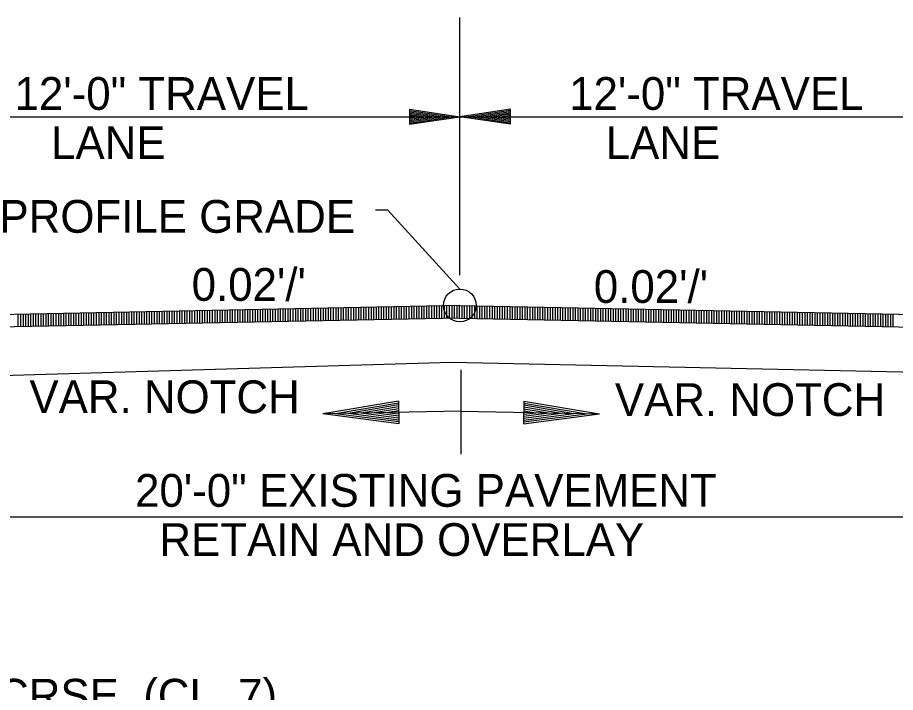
# Model space of a CAD drawing. Extents: x 1373719 to 1374161, y 379835 to 380167.
# Drawn here: x 1373956.25 to 1373973.66, y 380106.35 to 380119.74 of the extents above; entities that cross this region are included whole.
import ezdxf

# ---------------------------------------------------------------- set-up
doc = ezdxf.new("R2010")
doc.units = 0
for name, color, linetype in [('ACHM Surface', 7, 'Continuous'), ('Agg Base Course Text', 7, 'Continuous'), ('CL Construction', 7, 'Continuous'), ('GREEN_TXT', 7, 'Continuous'), ('T_Drafting', 7, 'Continuous')]:
    doc.layers.add(name, color=color, linetype=linetype)

msp = doc.modelspace()

# ---------------------------------------------------------------- linework, layer by layer
for p, q in [((1373965.018, 380114.03), (1373954.02, 380113.81)), ((1373965.018, 380114.03), (1373976.015, 380113.81)), ((1373965.018, 380113.78), (1373954.02, 380113.56)), ((1373965.018, 380113.78), (1373976.015, 380113.56))]:
    msp.add_line(p, q)
at = {"layer": 'ACHM Surface'}
for p, q in [((1373957.813, 380113.636), (1373957.813, 380113.886)), ((1373957.863, 380113.637), (1373957.863, 380113.887)), ((1373957.913, 380113.638), (1373957.913, 380113.888)), ((1373957.963, 380113.639), (1373957.963, 380113.889)), ((1373958.013, 380113.64), (1373958.013, 380113.89)), ((1373958.063, 380113.641), (1373958.063, 380113.891)), ((1373958.113, 380113.642), (1373958.113, 380113.892)), ((1373958.163, 380113.643), (1373958.163, 380113.893)), ((1373958.213, 380113.644), (1373958.213, 380113.894)), ((1373958.263, 380113.645), (1373958.263, 380113.895)), ((1373958.313, 380113.646), (1373958.313, 380113.896)), ((1373958.363, 380113.647), (1373958.363, 380113.897)), ((1373958.413, 380113.648), (1373958.413, 380113.898)), ((1373958.463, 380113.649), (1373958.463, 380113.899)), ((1373958.513, 380113.65), (1373958.513, 380113.9)), ((1373958.563, 380113.651), (1373958.563, 380113.901)), ((1373958.613, 380113.652), (1373958.613, 380113.902)), ((1373958.663, 380113.653), (1373958.663, 380113.903)), ((1373958.713, 380113.654), (1373958.713, 380113.904)), ((1373958.763, 380113.655), (1373958.763, 380113.905)), ((1373958.813, 380113.656), (1373958.813, 380113.906)), ((1373958.863, 380113.657), (1373958.863, 380113.907)), ((1373958.913, 380113.658), (1373958.913, 380113.908)), ((1373958.963, 380113.659), (1373958.963, 380113.909)), ((1373959.013, 380113.66), (1373959.013, 380113.91)), ((1373959.063, 380113.661), (1373959.063, 380113.911)), ((1373959.113, 380113.662), (1373959.113, 380113.912)), ((1373959.163, 380113.663), (1373959.163, 380113.913)), ((1373959.213, 380113.664), (1373959.213, 380113.914)), ((1373959.263, 380113.665), (1373959.263, 380113.915)), ((1373959.313, 380113.666), (1373959.313, 380113.916)), ((1373959.363, 380113.667), (1373959.363, 380113.917)), ((1373959.413, 380113.668), (1373959.413, 380113.918)), ((1373959.463, 380113.669), (1373959.463, 380113.919)), ((1373959.513, 380113.67), (1373959.513, 380113.92)), ((1373959.563, 380113.671), (1373959.563, 380113.921)), ((1373959.613, 380113.672), (1373959.613, 380113.922)), ((1373959.663, 380113.673), (1373959.663, 380113.923)), ((1373959.713, 380113.674), (1373959.713, 380113.924)), ((1373959.763, 380113.675), (1373959.763, 380113.925)), ((1373959.813, 380113.676), (1373959.813, 380113.926)), ((1373959.863, 380113.677), (1373959.863, 380113.927)), ((1373959.913, 380113.678), (1373959.913, 380113.928)), ((1373959.963, 380113.679), (1373959.963, 380113.929)), ((1373960.013, 380113.68), (1373960.013, 380113.93)), ((1373960.063, 380113.681), (1373960.063, 380113.931)), ((1373960.113, 380113.682), (1373960.113, 380113.932)), ((1373960.163, 380113.683), (1373960.163, 380113.933)), ((1373960.213, 380113.684), (1373960.213, 380113.934)), ((1373960.263, 380113.685), (1373960.263, 380113.935)), ((1373960.313, 380113.686), (1373960.313, 380113.936)), ((1373960.363, 380113.687), (1373960.363, 380113.937)), ((1373960.413, 380113.688), (1373960.413, 380113.938)), ((1373960.463, 380113.689), (1373960.463, 380113.939)), ((1373960.513, 380113.69), (1373960.513, 380113.94)), ((1373960.563, 380113.691), (1373960.563, 380113.941)), ((1373960.613, 380113.692), (1373960.613, 380113.942)), ((1373960.663, 380113.693), (1373960.663, 380113.943)), ((1373960.713, 380113.694), (1373960.713, 380113.944)), ((1373960.763, 380113.695), (1373960.763, 380113.945)), ((1373960.813, 380113.696), (1373960.813, 380113.946)), ((1373960.863, 380113.697), (1373960.863, 380113.947)), ((1373960.913, 380113.698), (1373960.913, 380113.948)), ((1373960.963, 380113.699), (1373960.963, 380113.949)), ((1373961.013, 380113.7), (1373961.013, 380113.95)), ((1373961.063, 380113.701), (1373961.063, 380113.951)), ((1373961.113, 380113.702), (1373961.113, 380113.952)), ((1373961.163, 380113.703), (1373961.163, 380113.953)), ((1373961.213, 380113.704), (1373961.213, 380113.954)), ((1373961.263, 380113.705), (1373961.263, 380113.955)), ((1373961.313, 380113.706), (1373961.313, 380113.956)), ((1373961.363, 380113.707), (1373961.363, 380113.957)), ((1373961.413, 380113.708), (1373961.413, 380113.958)), ((1373961.463, 380113.709), (1373961.463, 380113.959)), ((1373961.513, 380113.71), (1373961.513, 380113.96)), ((1373961.563, 380113.711), (1373961.563, 380113.961)), ((1373961.613, 380113.712), (1373961.613, 380113.962)), ((1373961.663, 380113.713), (1373961.663, 380113.963)), ((1373961.713, 380113.714), (1373961.713, 380113.964)), ((1373961.763, 380113.715), (1373961.763, 380113.965)), ((1373961.813, 380113.716), (1373961.813, 380113.966)), ((1373961.863, 380113.717), (1373961.863, 380113.967)), ((1373961.913, 380113.718), (1373961.913, 380113.968)), ((1373961.963, 380113.719), (1373961.963, 380113.969)), ((1373962.013, 380113.72), (1373962.013, 380113.97)), ((1373962.063, 380113.721), (1373962.063, 380113.971)), ((1373962.113, 380113.722), (1373962.113, 380113.972)), ((1373962.163, 380113.723), (1373962.163, 380113.973)), ((1373962.213, 380113.724), (1373962.213, 380113.974)), ((1373962.263, 380113.725), (1373962.263, 380113.975)), ((1373962.313, 380113.726), (1373962.313, 380113.976)), ((1373962.363, 380113.727), (1373962.363, 380113.977)), ((1373962.413, 380113.728), (1373962.413, 380113.978)), ((1373962.463, 380113.729), (1373962.463, 380113.979)), ((1373962.513, 380113.73), (1373962.513, 380113.98)), ((1373962.563, 380113.731), (1373962.563, 380113.981)), ((1373962.613, 380113.732), (1373962.613, 380113.982)), ((1373962.663, 380113.733), (1373962.663, 380113.983)), ((1373962.713, 380113.734), (1373962.713, 380113.984)), ((1373962.763, 380113.735), (1373962.763, 380113.985)), ((1373962.813, 380113.736), (1373962.813, 380113.986)), ((1373962.863, 380113.737), (1373962.863, 380113.987)), ((1373962.913, 380113.738), (1373962.913, 380113.988)), ((1373962.963, 380113.739), (1373962.963, 380113.989)), ((1373963.013, 380113.74), (1373963.013, 380113.99)), ((1373963.063, 380113.741), (1373963.063, 380113.991)), ((1373963.113, 380113.742), (1373963.113, 380113.992)), ((1373963.163, 380113.743), (1373963.163, 380113.993)), ((1373963.213, 380113.744), (1373963.213, 380113.994)), ((1373963.263, 380113.745), (1373963.263, 380113.995)), ((1373963.313, 380113.746), (1373963.313, 380113.996)), ((1373963.363, 380113.747), (1373963.363, 380113.997)), ((1373963.413, 380113.748), (1373963.413, 380113.998)), ((1373963.463, 380113.749), (1373963.463, 380113.999)), ((1373963.513, 380113.75), (1373963.513, 380114)), ((1373963.563, 380113.751), (1373963.563, 380114.001)), ((1373963.613, 380113.752), (1373963.613, 380114.002)), ((1373963.663, 380113.753), (1373963.663, 380114.003)), ((1373963.713, 380113.754), (1373963.713, 380114.004)), ((1373963.763, 380113.755), (1373963.763, 380114.005)), ((1373963.813, 380113.756), (1373963.813, 380114.006)), ((1373963.863, 380113.757), (1373963.863, 380114.007)), ((1373963.913, 380113.758), (1373963.913, 380114.008)), ((1373963.963, 380113.759), (1373963.963, 380114.009)), ((1373964.013, 380113.76), (1373964.013, 380114.01)), ((1373964.063, 380113.761), (1373964.063, 380114.011)), ((1373964.113, 380113.762), (1373964.113, 380114.012)), ((1373964.163, 380113.763), (1373964.163, 380114.013)), ((1373964.213, 380113.764), (1373964.213, 380114.014)), ((1373964.263, 380113.765), (1373964.263, 380114.015)), ((1373964.313, 380113.766), (1373964.313, 380114.016)), ((1373964.363, 380113.767), (1373964.363, 380114.017)), ((1373964.413, 380113.768), (1373964.413, 380114.018)), ((1373964.463, 380113.769), (1373964.463, 380114.019)), ((1373964.513, 380113.77), (1373964.513, 380114.02)), ((1373964.563, 380113.771), (1373964.563, 380114.021)), ((1373964.613, 380113.772), (1373964.613, 380114.022)), ((1373964.663, 380113.773), (1373964.663, 380114.023)), ((1373964.713, 380113.774), (1373964.713, 380114.024)), ((1373964.763, 380113.775), (1373964.763, 380114.025)), ((1373964.813, 380113.776), (1373964.813, 380114.026)), ((1373964.863, 380113.777), (1373964.863, 380114.027)), ((1373964.913, 380113.778), (1373964.913, 380114.028)), ((1373964.963, 380113.779), (1373964.963, 380114.029)), ((1373965.013, 380113.78), (1373965.013, 380114.03)), ((1373965.063, 380113.779), (1373965.063, 380114.029)), ((1373965.113, 380113.778), (1373965.113, 380114.028)), ((1373965.163, 380113.777), (1373965.163, 380114.027)), ((1373965.213, 380113.776), (1373965.213, 380114.026)), ((1373965.263, 380113.775), (1373965.263, 380114.025)), ((1373965.313, 380113.774), (1373965.313, 380114.024)), ((1373965.363, 380113.773), (1373965.363, 380114.023)), ((1373965.413, 380113.772), (1373965.413, 380114.022)), ((1373965.463, 380113.771), (1373965.463, 380114.021)), ((1373965.513, 380113.77), (1373965.513, 380114.02)), ((1373965.563, 380113.769), (1373965.563, 380114.019)), ((1373965.613, 380113.768), (1373965.613, 380114.018)), ((1373965.663, 380113.767), (1373965.663, 380114.017)), ((1373965.713, 380113.766), (1373965.713, 380114.016)), ((1373965.763, 380113.765), (1373965.763, 380114.015)), ((1373965.813, 380113.764), (1373965.813, 380114.014)), ((1373965.863, 380113.763), (1373965.863, 380114.013)), ((1373965.913, 380113.762), (1373965.913, 380114.012)), ((1373965.963, 380113.761), (1373965.963, 380114.011)), ((1373966.013, 380113.76), (1373966.013, 380114.01)), ((1373966.063, 380113.759), (1373966.063, 380114.009)), ((1373966.113, 380113.758), (1373966.113, 380114.008)), ((1373966.163, 380113.757), (1373966.163, 380114.007)), ((1373966.213, 380113.756), (1373966.213, 380114.006)), ((1373966.263, 380113.755), (1373966.263, 380114.005)), ((1373966.313, 380113.754), (1373966.313, 380114.004)), ((1373966.363, 380113.753), (1373966.363, 380114.003)), ((1373966.413, 380113.752), (1373966.413, 380114.002)), ((1373966.463, 380113.751), (1373966.463, 380114.001)), ((1373966.513, 380113.75), (1373966.513, 380114)), ((1373966.563, 380113.749), (1373966.563, 380113.999)), ((1373966.613, 380113.748), (1373966.613, 380113.998)), ((1373966.663, 380113.747), (1373966.663, 380113.997)), ((1373966.713, 380113.746), (1373966.713, 380113.996)), ((1373966.763, 380113.745), (1373966.763, 380113.995)), ((1373966.813, 380113.744), (1373966.813, 380113.994)), ((1373966.863, 380113.743), (1373966.863, 380113.993)), ((1373966.913, 380113.742), (1373966.913, 380113.992)), ((1373966.963, 380113.741), (1373966.963, 380113.991)), ((1373967.013, 380113.74), (1373967.013, 380113.99)), ((1373967.063, 380113.739), (1373967.063, 380113.989)), ((1373967.113, 380113.738), (1373967.113, 380113.988)), ((1373967.163, 380113.737), (1373967.163, 380113.987)), ((1373967.213, 380113.736), (1373967.213, 380113.986)), ((1373967.263, 380113.735), (1373967.263, 380113.985)), ((1373967.313, 380113.734), (1373967.313, 380113.984)), ((1373967.363, 380113.733), (1373967.363, 380113.983)), ((1373967.413, 380113.732), (1373967.413, 380113.982)), ((1373967.463, 380113.731), (1373967.463, 380113.981)), ((1373967.513, 380113.73), (1373967.513, 380113.98)), ((1373967.563, 380113.729), (1373967.563, 380113.979)), ((1373967.613, 380113.728), (1373967.613, 380113.978)), ((1373967.663, 380113.727), (1373967.663, 380113.977)), ((1373967.713, 380113.726), (1373967.713, 380113.976)), ((1373967.763, 380113.725), (1373967.763, 380113.975)), ((1373967.813, 380113.724), (1373967.813, 380113.974)), ((1373967.863, 380113.723), (1373967.863, 380113.973)), ((1373967.913, 380113.722), (1373967.913, 380113.972)), ((1373967.963, 380113.721), (1373967.963, 380113.971)), ((1373968.013, 380113.72), (1373968.013, 380113.97)), ((1373968.063, 380113.719), (1373968.063, 380113.969)), ((1373968.113, 380113.718), (1373968.113, 380113.968)), ((1373968.163, 380113.717), (1373968.163, 380113.967)), ((1373968.213, 380113.716), (1373968.213, 380113.966)), ((1373968.263, 380113.715), (1373968.263, 380113.965)), ((1373968.313, 380113.714), (1373968.313, 380113.964)), ((1373968.363, 380113.713), (1373968.363, 380113.963)), ((1373968.413, 380113.712), (1373968.413, 380113.962)), ((1373968.463, 380113.711), (1373968.463, 380113.961)), ((1373968.513, 380113.71), (1373968.513, 380113.96)), ((1373968.563, 380113.709), (1373968.563, 380113.959)), ((1373968.613, 380113.708), (1373968.613, 380113.958)), ((1373968.663, 380113.707), (1373968.663, 380113.957)), ((1373968.713, 380113.706), (1373968.713, 380113.956)), ((1373968.763, 380113.705), (1373968.763, 380113.955)), ((1373968.813, 380113.704), (1373968.813, 380113.954)), ((1373968.863, 380113.703), (1373968.863, 380113.953)), ((1373968.913, 380113.702), (1373968.913, 380113.952)), ((1373968.963, 380113.701), (1373968.963, 380113.951)), ((1373969.013, 380113.7), (1373969.013, 380113.95)), ((1373969.063, 380113.699), (1373969.063, 380113.949)), ((1373969.113, 380113.698), (1373969.113, 380113.948)), ((1373969.163, 380113.697), (1373969.163, 380113.947)), ((1373969.213, 380113.696), (1373969.213, 380113.946)), ((1373969.263, 380113.695), (1373969.263, 380113.945)), ((1373969.313, 380113.694), (1373969.313, 380113.944)), ((1373969.363, 380113.693), (1373969.363, 380113.943)), ((1373969.413, 380113.692), (1373969.413, 380113.942)), ((1373969.463, 380113.691), (1373969.463, 380113.941)), ((1373969.513, 380113.69), (1373969.513, 380113.94)), ((1373969.563, 380113.689), (1373969.563, 380113.939)), ((1373969.613, 380113.688), (1373969.613, 380113.938)), ((1373969.663, 380113.687), (1373969.663, 380113.937)), ((1373969.713, 380113.686), (1373969.713, 380113.936)), ((1373969.763, 380113.685), (1373969.763, 380113.935)), ((1373969.813, 380113.684), (1373969.813, 380113.934)), ((1373969.863, 380113.683), (1373969.863, 380113.933)), ((1373969.913, 380113.682), (1373969.913, 380113.932)), ((1373969.963, 380113.681), (1373969.963, 380113.931)), ((1373970.013, 380113.68), (1373970.013, 380113.93)), ((1373970.063, 380113.679), (1373970.063, 380113.929)), ((1373970.113, 380113.678), (1373970.113, 380113.928)), ((1373970.163, 380113.677), (1373970.163, 380113.927)), ((1373970.213, 380113.676), (1373970.213, 380113.926)), ((1373970.263, 380113.675), (1373970.263, 380113.925)), ((1373970.313, 380113.674), (1373970.313, 380113.924)), ((1373970.363, 380113.673), (1373970.363, 380113.923)), ((1373970.413, 380113.672), (1373970.413, 380113.922)), ((1373970.463, 380113.671), (1373970.463, 380113.921)), ((1373970.513, 380113.67), (1373970.513, 380113.92)), ((1373970.563, 380113.669), (1373970.563, 380113.919)), ((1373970.613, 380113.668), (1373970.613, 380113.918)), ((1373970.663, 380113.667), (1373970.663, 380113.917)), ((1373970.713, 380113.666), (1373970.713, 380113.916)), ((1373970.763, 380113.665), (1373970.763, 380113.915)), ((1373970.813, 380113.664), (1373970.813, 380113.914)), ((1373970.863, 380113.663), (1373970.863, 380113.913)), ((1373970.913, 380113.662), (1373970.913, 380113.912)), ((1373970.963, 380113.661), (1373970.963, 380113.911)), ((1373971.013, 380113.66), (1373971.013, 380113.91)), ((1373971.063, 380113.659), (1373971.063, 380113.909)), ((1373971.113, 380113.658), (1373971.113, 380113.908)), ((1373971.163, 380113.657), (1373971.163, 380113.907)), ((1373971.213, 380113.656), (1373971.213, 380113.906)), ((1373971.263, 380113.655), (1373971.263, 380113.905)), ((1373971.313, 380113.654), (1373971.313, 380113.904)), ((1373971.363, 380113.653), (1373971.363, 380113.903)), ((1373971.413, 380113.652), (1373971.413, 380113.902)), ((1373971.463, 380113.651), (1373971.463, 380113.901)), ((1373971.513, 380113.65), (1373971.513, 380113.9)), ((1373971.563, 380113.649), (1373971.563, 380113.899)), ((1373971.613, 380113.648), (1373971.613, 380113.898)), ((1373971.663, 380113.647), (1373971.663, 380113.897)), ((1373971.713, 380113.646), (1373971.713, 380113.896)), ((1373971.763, 380113.645), (1373971.763, 380113.895)), ((1373971.813, 380113.644), (1373971.813, 380113.894)), ((1373971.863, 380113.643), (1373971.863, 380113.893)), ((1373971.913, 380113.642), (1373971.913, 380113.892)), ((1373971.963, 380113.641), (1373971.963, 380113.891)), ((1373972.013, 380113.64), (1373972.013, 380113.89)), ((1373972.063, 380113.639), (1373972.063, 380113.889)), ((1373972.113, 380113.638), (1373972.113, 380113.888)), ((1373972.163, 380113.637), (1373972.163, 380113.887)), ((1373972.213, 380113.636), (1373972.213, 380113.886)), ((1373956.263, 380113.605), (1373956.263, 380113.855)), ((1373956.313, 380113.606), (1373956.313, 380113.856)), ((1373956.363, 380113.607), (1373956.363, 380113.857)), ((1373956.413, 380113.608), (1373956.413, 380113.858)), ((1373956.463, 380113.609), (1373956.463, 380113.859)), ((1373956.513, 380113.61), (1373956.513, 380113.86)), ((1373956.563, 380113.611), (1373956.563, 380113.861)), ((1373956.613, 380113.612), (1373956.613, 380113.862)), ((1373956.663, 380113.613), (1373956.663, 380113.863)), ((1373956.713, 380113.614), (1373956.713, 380113.864)), ((1373956.763, 380113.615), (1373956.763, 380113.865)), ((1373956.813, 380113.616), (1373956.813, 380113.866)), ((1373956.863, 380113.617), (1373956.863, 380113.867)), ((1373956.913, 380113.618), (1373956.913, 380113.868)), ((1373956.963, 380113.619), (1373956.963, 380113.869)), ((1373957.013, 380113.62), (1373957.013, 380113.87)), ((1373957.063, 380113.621), (1373957.063, 380113.871)), ((1373957.113, 380113.622), (1373957.113, 380113.872)), ((1373957.163, 380113.623), (1373957.163, 380113.873)), ((1373957.213, 380113.624), (1373957.213, 380113.874)), ((1373957.263, 380113.625), (1373957.263, 380113.875)), ((1373957.313, 380113.626), (1373957.313, 380113.876)), ((1373957.363, 380113.627), (1373957.363, 380113.877)), ((1373957.413, 380113.628), (1373957.413, 380113.878)), ((1373957.463, 380113.629), (1373957.463, 380113.879)), ((1373957.513, 380113.63), (1373957.513, 380113.88)), ((1373957.563, 380113.631), (1373957.563, 380113.881)), ((1373957.613, 380113.632), (1373957.613, 380113.882)), ((1373957.663, 380113.633), (1373957.663, 380113.883)), ((1373957.713, 380113.634), (1373957.713, 380113.884)), ((1373957.763, 380113.635), (1373957.763, 380113.885)), ((1373972.263, 380113.635), (1373972.263, 380113.885)), ((1373972.313, 380113.634), (1373972.313, 380113.884)), ((1373972.363, 380113.633), (1373972.363, 380113.883)), ((1373972.413, 380113.632), (1373972.413, 380113.882)), ((1373972.463, 380113.631), (1373972.463, 380113.881)), ((1373972.513, 380113.63), (1373972.513, 380113.88)), ((1373972.563, 380113.629), (1373972.563, 380113.879)), ((1373972.613, 380113.628), (1373972.613, 380113.878)), ((1373972.663, 380113.627), (1373972.663, 380113.877)), ((1373972.713, 380113.626), (1373972.713, 380113.876)), ((1373972.763, 380113.625), (1373972.763, 380113.875)), ((1373972.813, 380113.624), (1373972.813, 380113.874)), ((1373972.863, 380113.623), (1373972.863, 380113.873)), ((1373972.913, 380113.622), (1373972.913, 380113.872)), ((1373972.963, 380113.621), (1373972.963, 380113.871)), ((1373973.013, 380113.62), (1373973.013, 380113.87)), ((1373973.063, 380113.619), (1373973.063, 380113.869)), ((1373973.113, 380113.618), (1373973.113, 380113.868)), ((1373973.163, 380113.617), (1373973.163, 380113.867)), ((1373973.213, 380113.616), (1373973.213, 380113.866)), ((1373973.263, 380113.615), (1373973.263, 380113.865)), ((1373973.313, 380113.614), (1373973.313, 380113.864)), ((1373973.363, 380113.613), (1373973.363, 380113.863)), ((1373973.413, 380113.612), (1373973.413, 380113.862)), ((1373973.463, 380113.611), (1373973.463, 380113.861)), ((1373973.513, 380113.61), (1373973.513, 380113.86)), ((1373973.563, 380113.609), (1373973.563, 380113.859)), ((1373973.613, 380113.608), (1373973.613, 380113.858))]:
    msp.add_line(p, q, dxfattribs=at)
at = {"layer": 'CL Construction'}
msp.add_line((1373965.018, 380114.627), (1373965.018, 380119.74), dxfattribs=at)
at = {"layer": 'GREEN_TXT'}
for p, q in [((1373964.02, 380117.922), (1373965.02, 380117.772)), ((1373964.02, 380117.922), (1373964.02, 380117.622)), ((1373964.02, 380117.897), (1373964.853, 380117.772)), ((1373966.02, 380117.922), (1373965.02, 380117.772)), ((1373966.02, 380117.897), (1373965.187, 380117.772)), ((1373966.02, 380117.622), (1373966.02, 380117.922)), ((1373954.02, 380117.772), (1373976.02, 380117.772)), ((1373964.02, 380117.871), (1373964.681, 380117.772)), ((1373964.02, 380117.846), (1373964.514, 380117.772)), ((1373964.02, 380117.82), (1373964.345, 380117.772)), ((1373964.02, 380117.795), (1373964.178, 380117.772)), ((1373964.02, 380117.622), (1373965.02, 380117.772)), ((1373964.02, 380117.723), (1373964.345, 380117.772)), ((1373964.02, 380117.672), (1373964.681, 380117.772)), ((1373964.02, 380117.647), (1373964.853, 380117.772)), ((1373964.02, 380117.697), (1373964.514, 380117.772)), ((1373964.02, 380117.748), (1373964.178, 380117.772)), ((1373966.02, 380117.622), (1373965.02, 380117.772)), ((1373966.02, 380117.647), (1373965.187, 380117.772)), ((1373966.02, 380117.871), (1373965.359, 380117.772)), ((1373966.02, 380117.672), (1373965.359, 380117.772)), ((1373966.02, 380117.846), (1373965.525, 380117.772)), ((1373966.02, 380117.697), (1373965.525, 380117.772)), ((1373966.02, 380117.821), (1373965.695, 380117.772)), ((1373966.02, 380117.723), (1373965.695, 380117.772)), ((1373966.02, 380117.795), (1373965.862, 380117.772)), ((1373966.02, 380117.748), (1373965.862, 380117.772)), ((1373965.044, 380111.081), (1373965.044, 380112.754)), ((1373963.799, 380112.132), (1373962.304, 380111.878)), ((1373963.8, 380112.094), (1373962.554, 380111.883)), ((1373963.8, 380112.055), (1373962.812, 380111.888)), ((1373963.801, 380112.018), (1373963.062, 380111.893)), ((1373963.802, 380111.979), (1373963.316, 380111.897)), ((1373963.799, 380112.132), (1373963.808, 380111.682)), ((1373966.29, 380112.132), (1373966.281, 380111.682)), ((1373966.287, 380111.979), (1373966.773, 380111.897)), ((1373966.288, 380112.055), (1373967.277, 380111.888)), ((1373966.288, 380112.018), (1373967.026, 380111.893)), ((1373966.289, 380112.094), (1373967.535, 380111.883)), ((1373966.29, 380112.132), (1373967.785, 380111.878)), ((1373965.044, 380111.931), (1373962.304, 380111.878)), ((1373963.808, 380111.682), (1373962.304, 380111.878)), ((1373963.807, 380111.719), (1373962.554, 380111.883)), ((1373963.806, 380111.757), (1373962.812, 380111.888)), ((1373963.805, 380111.794), (1373963.062, 380111.893)), ((1373963.805, 380111.833), (1373963.316, 380111.897)), ((1373963.803, 380111.941), (1373963.566, 380111.902)), ((1373963.804, 380111.871), (1373963.566, 380111.902)), ((1373965.044, 380111.931), (1373967.785, 380111.878)), ((1373966.281, 380111.682), (1373967.785, 380111.878)), ((1373966.282, 380111.719), (1373967.535, 380111.883)), ((1373966.283, 380111.794), (1373967.026, 380111.893)), ((1373966.283, 380111.757), (1373967.277, 380111.888)), ((1373966.284, 380111.833), (1373966.773, 380111.897)), ((1373966.285, 380111.871), (1373966.523, 380111.902)), ((1373966.286, 380111.941), (1373966.523, 380111.902)), ((1373975.044, 380109.832), (1373955.044, 380109.832))]:
    msp.add_line(p, q, dxfattribs=at)
msp.add_lwpolyline([(1373965.018, 380114.355), (1373963.591, 380115.917), (1373963.347, 380115.92)], dxfattribs=at)
msp.add_circle((1373965.018, 380114.03), 0.325, dxfattribs=at)
at = {"layer": 'T_Drafting'}
msp.add_lwpolyline([(1373907.987, 380106.564), (1373924.533, 380106.487), (1373943.45, 380108.654), (1373953.585, 380112.614), (1373955.026, 380112.615), (1373964.851, 380112.903), (1373975.028, 380112.689), (1373976.603, 380112.615), (1373985.688, 380110.353), (1373993.989, 380112.909), (1374008.917, 380113.95), (1374025.023, 380113.95)], dxfattribs=at)

# ---------------------------------------------------------------- texts
at = {"layer": 'Agg Base Course Text'}
msp.add_text('2\'-0" AGGREGATE BASE CRSE. (CL. 7)', height=0.65, dxfattribs=at).set_placement((1373945.562, 380105.973))
at = {"layer": 'GREEN_TXT'}
for s, p in [('12\'-0" TRAVEL ', (1373956.188, 380117.909)), ('12\'-0" TRAVEL ', (1373967.186, 380117.909)), ('   LANE', (1373956.188, 380116.934)), ('   LANE', (1373967.186, 380116.934)), ('20\'-0" EXISTING PAVEMENT', (1373958.578, 380110.036)), ('  RETAIN AND OVERLAY', (1373958.578, 380109.061))]:
    msp.add_text(s, height=0.65, dxfattribs=at).set_placement(p)
for s, rotation, p in [('PROFILE GRADE', 359.98, (1373955.889, 380115.472)), ("0.02'/'", 359.98, (1373959.7, 380114.121)), ("0.02'/'", 359.98, (1373967.675, 380114.08)), ('VAR. NOTCH', 359.98, (1373956.483, 380111.894)), ('VAR. NOTCH', 0.02, (1373968.092, 380111.836))]:
    msp.add_text(s, height=0.65, rotation=rotation, dxfattribs=at).set_placement(p)

doc.saveas('drawing.dxf')
